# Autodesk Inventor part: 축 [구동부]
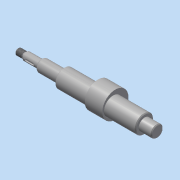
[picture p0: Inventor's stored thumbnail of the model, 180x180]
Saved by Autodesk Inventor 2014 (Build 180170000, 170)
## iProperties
Created: 2015-12
Part Number: 축 [구동부]
Document SubType Name: Modeling
Designer: mdu
Density: 7.86 g/cm^3
Material: 강철, 연강
Appearance: 강철
Mass: 484.681 g
Surface Area: 125.968 cm^2
Volume: 61.6642 cm^3
Author: mdu
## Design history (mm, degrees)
sketch "스케치1"
  geometry: L1 (62, 100.9)-(62, 67.1) reference; L2 (51, 101.2)-(51, 84) reference; L3 (-51, 84)-(-51, 101.2) reference; L4 (-62, 67.1)-(-62, 100.9) reference; L5 (-51.6, 91.5)-(-61.4, 91.5) reference; L6 (51.6, 91.5)-(61.4, 91.5) reference; L7 (67, 84)-(-109, 84); L8 (-77, 64.201)-(-77, 103.799) reference; L9 (67, 84)-(67, 91.5); L10 (67, 91.5)-(51, 91.5); L11 (51, 91.5)-(51, 95.5); L12 (51, 95.5)-(-51, 95.5); L13 (-51, 95.5)-(-51, 91.5); L14 (-51, 91.5)-(-79, 91.5); L15 (-79, 91.5)-(-79, 89); L16 (-79, 89)-(-99, 89); L17 (-99, 89)-(-99, 87); L18 (-100.5, 88)-(-109, 88); L19 (-109, 88)-(-109, 84); L20 (-99, 87)-(-100.5, 87); L21 (-100.5, 87)-(-100.5, 88); 2 further points
  constraints: 32 end point, 7 parallel, 6 point on line, 5 perpendicular, 2 collinear, 2 horizontal, 1 midpoint, 4 other
  dimensions: "d0" = 5 distance from line of L7.start L1; "d2" = 2 distance between parallel lines of L15 L8; "d3" = 23 diameter of L12 L7; "d4" = 10 diameter of L16 L7; "d5" = 1.5 distance of L17.end L20.end; "d6" = 6 diameter of L20 L7; "d7" = 20 distance of L15.end L16.end; "d8" = 10 distance between parallel lines of L17 L19; "d9" = 8 diameter of L18 L7
revolve "회전1" sketch "스케치1" stored, may be unused: angle "d10" = 90 deg
sketch "스케치2"
  geometry: C1 r 11.5 at (84, 0) reference; C2 r 11.5 at (84, 0) reference; C3 r 16.5 at (87, 0); 1 further point
  constraints: 1 centre point, 1 horizontal alignment
  dimensions: "d11" = 33 diameter of C3; "d12" = 3 distance of C3.centre C1.centre
extrude "돌출1" join sketch "스케치2" stored distance "d13" = 22; taper "d14" = 0 deg
chamfer "모따기1" distance "d15" = 1; stored, may be unused: second distance "d16" = 2, angle "d17" = 45 deg
feature "스레드1" dims "d18" = 10, "d19" = 0
node "작업 평면1"
sketch "스케치3"
  geometry: L1 (-5.5, -1.5)-(3.5, -1.5); L2 (3.5, 1.5)-(-5.5, 1.5); L3 (-10, -4)-(-10, 4) reference; A1 r 1.5 centre (3.5, 0) between (3.5, -1.5) and (3.5, 1.5); A2 r 1.5 centre (-5.5, 0) between (-5.5, 1.5) and (-5.5, -1.5); 2 further points
  constraints: 4 end point, 4 point on circle, 4 tangent, 2 centre point, 1 horizontal, 1 horizontal alignment, 1 midpoint, 1 parallel
  dimensions: "d20" = 3 distance between parallel lines of L1 L2; "d21" = 12 dimension on A1 A2; "d22" = 3 distance edge to line of A2 L3
extrude "돌출2" cut sketch "스케치3" distance "d23" = 1.8; taper "d24" = 0 deg
fillet "모깎기1" dims "d25" = 0.3
fillet "모깎기2" dims "d26" = 3
node "솔리드1"
node "참조1"
node "참조2"
node "참조3"
node "참조4"
node "참조5"
node "투영된 루프1"
